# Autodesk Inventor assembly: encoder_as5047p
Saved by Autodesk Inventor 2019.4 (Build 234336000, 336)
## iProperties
Created: 2020-10
Part Number: encoder_as5047p
Document SubType Name: Assembly
Designer: Administrator
Title: encoder_as5047p v1
Author: Administrator
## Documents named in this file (3)
- c:\worker\convert-fusion-r08\tmp\job-1\12\output\files\adb68884-feb4-4781-9d80-27ec745be401\5a9cbf7a-fc17-4ce8-9f10-8a79054ca41d.zip.iam
- c:\worker\convert-fusion-r08\tmp\job-1\12\output\files\adb68884-feb4-4781-9d80-27ec745be401\Board.ipt
- c:\worker\convert-fusion-r08\tmp\job-1\12\output\files\adb68884-feb4-4781-9d80-27ec745be401\Packages.iam
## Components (2 placed, 2 different names)
1. Board:1
2. Packages:1 [sub-assembly]
